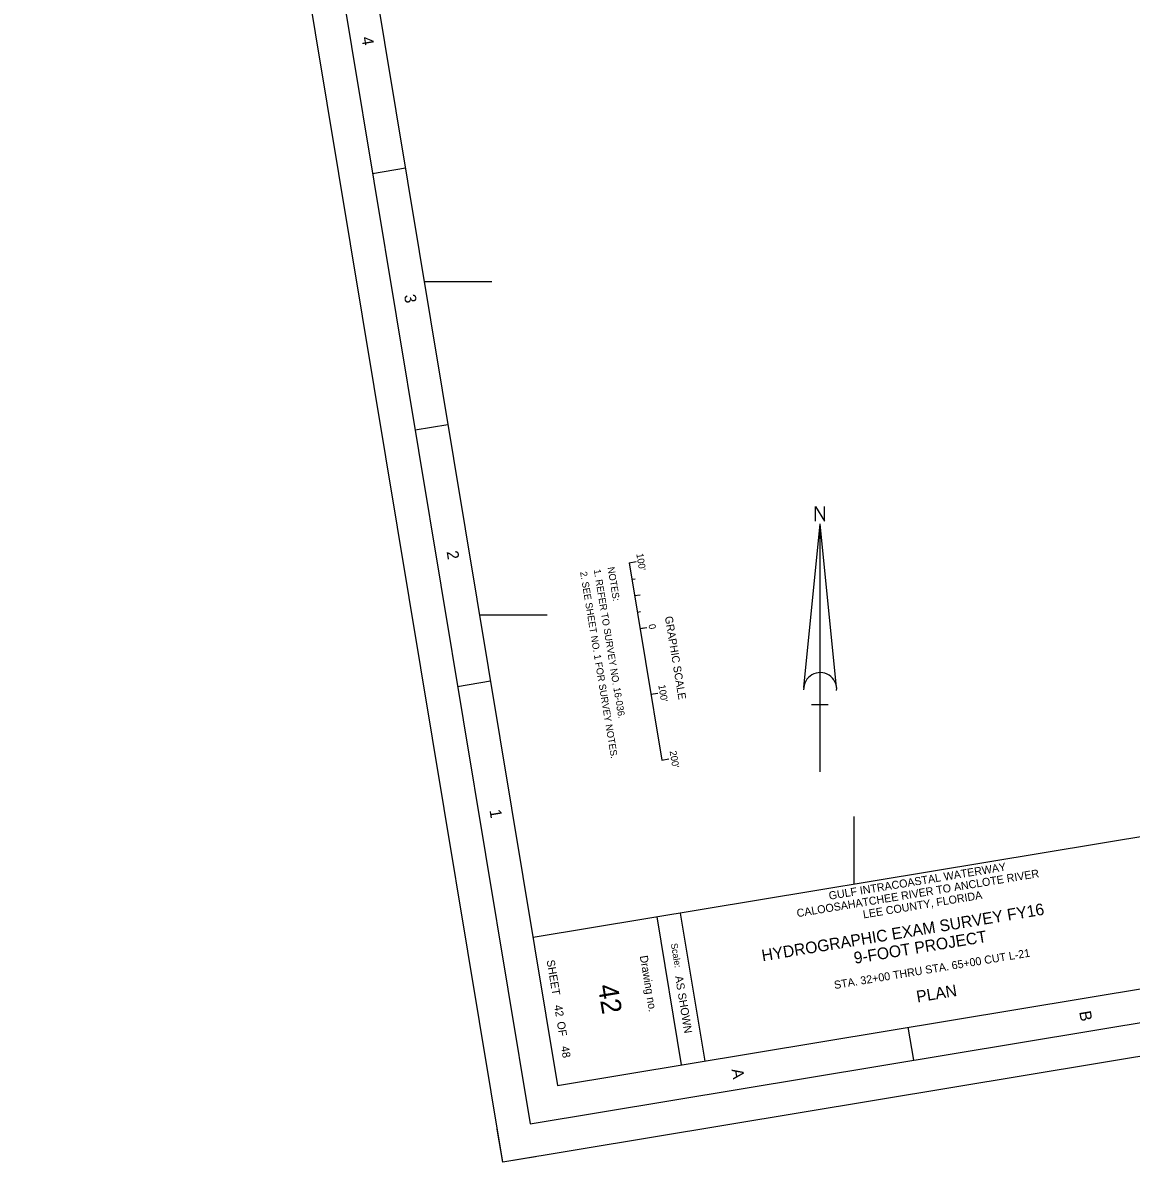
# Model space of a CAD drawing. Extents: x 574253 to 578327, y 864179 to 869076.
# Drawn here: x 574253 to 575916, y 864179 to 865888 of the extents above; entities that cross this region are included whole.
import ezdxf

# ---------------------------------------------------------------- set-up
doc = ezdxf.new("R2010")
doc.units = 0
for name, color, linetype in [('G-ANNO-NPLT', 7, 'Continuous'), ('G-ANNO-TEXT-DRWG', 7, 'Continuous'), ('G-ANNO-TEXT-PROJ', 7, 'Continuous'), ('G-ANNO-TEXT-TTLB', 7, 'Continuous'), ('G-ANNO-TTLB', 7, 'Continuous'), ('V-ANNO-NOTE', 7, 'Continuous'), ('V-ANNO-SYMB', 7, 'Continuous'), ('V-TOPO-COOR-STAT', 7, 'Continuous')]:
    doc.layers.add(name, color=color, linetype=linetype)

msp = doc.modelspace()

# ---------------------------------------------------------------- linework, layer by layer
at = {"layer": 'G-ANNO-NPLT'}
msp.add_lwpolyline([(577607.4, 869075.9), (578327.2, 864735.2), (574973, 864179), (574253.2, 868519.7)], close=True, dxfattribs=at)
msp.add_lwpolyline([(575022.4, 864187.1), (574973.1, 864178.9), (574964.9, 864228.2)], dxfattribs=at)
at = {"layer": 'G-ANNO-TTLB'}
for p, q in [((574777.8, 865662), (574827.1, 865670.2)), ((574841.6, 865277.3), (574890.9, 865285.5)), ((578175.4, 865039.5), (575018.5, 864516)), ((574905.4, 864892.6), (574954.7, 864900.7)), ((575204.1, 864546.8), (575240.9, 864324.8)), ((575239.3, 864552.6), (575276.1, 864330.6)), ((575589.6, 864331.9), (575581.4, 864381.3))]:
    msp.add_line(p, q, dxfattribs=at)
for points in [[(574310.7, 868478.6), (575014.2, 864236.5), (578269.7, 864776.4), (577566.3, 869018.4)], [(578212.2, 864817.5), (577537.4, 868886.9), (574380.5, 868363.4), (575055.3, 864294)]]:
    msp.add_lwpolyline(points, close=True, dxfattribs=at)
at = {"layer": 'V-ANNO-NOTE'}
for p, q in [((575162.7, 865078), (575173, 865079.7)), ((575162.7, 865078), (575211.8, 864782.1)), ((575166.8, 865053.4), (575171.5, 865054.1)), ((575170.9, 865028.7), (575179.3, 865030.1)), ((575175, 865004), (575179.7, 865004.8)), ((575179, 864979.4), (575189.3, 864981.1)), ((575179, 864979.4), (575189.3, 864981.1)), ((575179, 864979.4), (575184, 864980.2)), ((575195.4, 864880.7), (575205.7, 864882.4)), ((575211.8, 864782.1), (575222.1, 864783.8))]:
    msp.add_line(p, q, dxfattribs=at)
at = {"layer": 'V-ANNO-SYMB'}
for p, q in [((575424.5, 864890.8), (575449.2, 865136.6)), ((575449.2, 864764.2), (575449.2, 865136.6)), ((575473.9, 864890.8), (575449.2, 865136.6)), ((575461, 864864.8), (575436.1, 864864.8))]:
    msp.add_line(p, q, dxfattribs=at)
msp.add_lwpolyline([(575442.3, 865140.6), (575442.3, 865162.3), (575455.8, 865140.6), (575455.8, 865162.3)], dxfattribs=at)
msp.add_arc((575449.2, 864888.4), 24.8, 355.2984, 182.0673, dxfattribs=at)
at = {"layer": 'V-TOPO-COOR-STAT'}
for p, q in [((574855.3, 865500), (574956.7, 865500)), ((574938.3, 865000), (575039.6, 865000)), ((575500, 864595.9), (575500, 864697.2))]:
    msp.add_line(p, q, dxfattribs=at)

# ---------------------------------------------------------------- texts
at = {"layer": 'G-ANNO-TEXT-DRWG'}
for s, height, rotation, p in [('STA. 32+00 THRU STA. 65+00 CUT L-21', 12, 9.4155, (575471, 864438.6)), ('42', 30, 279.4155, (575115.5, 864443.5)), ('PLAN', 17.5, 9.4155, (575595, 864418.4)), (' 42          48', 12, 279.4155, (575049.4, 864418.2))]:
    msp.add_text(s, height=height, rotation=rotation, dxfattribs=at).set_placement(p)
at = {"layer": 'G-ANNO-TEXT-PROJ'}
for s, height, p in [('GULF INTRACOASTAL WATERWAY', 12, (575463.1, 864572.5)), ('CALOOSAHATCHEE RIVER TO ANCLOTE RIVER', 12, (575415, 864546.3)), ('LEE COUNTY, FLORIDA', 12, (575514.4, 864544.5)), ('HYDROGRAPHIC EXAM SURVEY FY16', 17.5, (575362.9, 864480.1)), ('9-FOOT PROJECT', 17.5, (575501.2, 864476.4))]:
    msp.add_text(s, height=height, rotation=9.4155, dxfattribs=at).set_placement(p)
at = {"layer": 'G-ANNO-TEXT-TTLB'}
for s, height, p in [('Scale:', 10, (575225.2, 864506.6)), ('Drawing no.', 12, (575178.6, 864488)), ('SHEET         OF', 12, (575038.9, 864481.4)), ('AS SHOWN', 12, (575231.4, 864457.6))]:
    msp.add_text(s, height=height, rotation=279.4155, dxfattribs=at).set_placement(p)
at = {"layer": 'G-ANNO-TTLB'}
for s, p in [('4', (574760.9, 865865.7)), ('3', (574825, 865479.2)), ('2', (574888.8, 865094.6)), ('1', (574953.1, 864706.8)), ('B', (575837.7, 864404.5)), ('A', (575316.1, 864318))]:
    msp.add_text(s, height=17.5, rotation=279.4155, dxfattribs=at).set_placement(p)
at = {"layer": 'V-ANNO-NOTE'}
for s, height, p in [("100'", 10.42, (575173.4, 865091.3)), ('NOTES:', 10.42, (575130.2, 865070.9)), ('2. SEE SHEET NO. 1 FOR SURVEY NOTES.', 10.416, (575089.1, 865064)), ('1. REFER TO SURVEY NO. 16-036.', 10.416, (575109.6, 865067.4)), ('0', 10.4, (575191.7, 864985.2)), ('GRAPHIC SCALE', 11.666, (575216.2, 864996.9)), ("100'", 10.42, (575206.4, 864894.3)), ("200'", 10.42, (575223.4, 864795.2))]:
    msp.add_text(s, height=height, rotation=279.4155, dxfattribs=at).set_placement(p)

doc.saveas('drawing.dxf')
